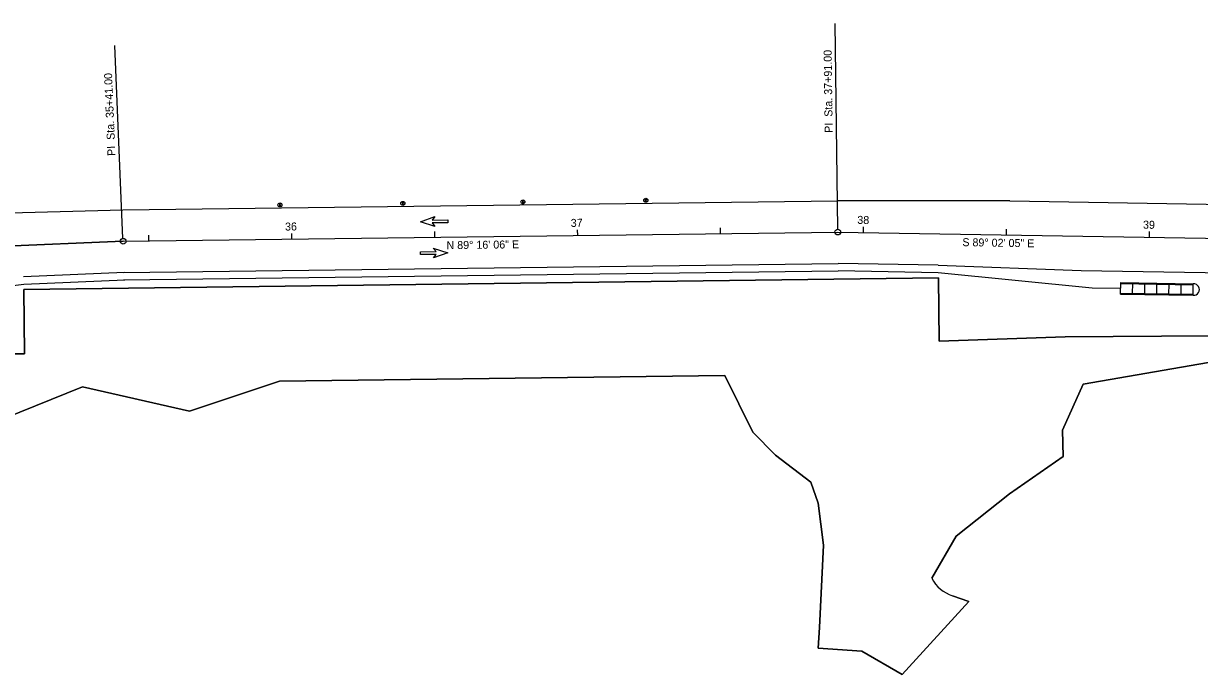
# Model space of a CAD drawing. Extents: x 2336268 to 2337731, y 629406 to 629656.
# Drawn here: x 2336849.2 to 2337260.6, y 629406.1 to 629633.9 of the extents above; entities that cross this region are included whole.
import ezdxf

# ---------------------------------------------------------------- set-up
doc = ezdxf.new("R2010")
doc.units = 0
for name, color, linetype in [('DR_P_Cells', 7, 'Continuous'), ('GE_P_CL_20', 7, 'Continuous'), ('GK_Drainage_Nodes', 7, 'Continuous'), ('MT_P_Cells', 7, 'Continuous'), ('MT_P_CL_Double_Solid', 7, 'Continuous'), ('MT_P_Edge_Line', 7, 'Continuous'), ('MT_P_PCB', 7, 'Continuous'), ('MT_P_Work_Area', 7, 'Continuous'), ('RD_P_Anchor_Assembly', 7, 'Continuous')]:
    doc.layers.add(name, color=color, linetype=linetype)

msp = doc.modelspace()

# ---------------------------------------------------------------- linework, layer by layer
at = {"layer": 'DR_P_Cells'}
for points in [[(2336981.99, 629571.33), (2336981.71, 629571.33), (2336981.72, 629570.53), (2336982, 629570.53)], [(2337023.99, 629571.87), (2337023.71, 629571.86), (2337023.72, 629571.06), (2337024, 629571.07)], [(2337066.98, 629572.41), (2337066.7, 629572.41), (2337066.71, 629571.61), (2337066.99, 629571.61)], [(2336938.99, 629570.78), (2336938.71, 629570.78), (2336938.72, 629569.98), (2336939, 629569.98)]]:
    msp.add_lwpolyline(points, dxfattribs=at)
for centre in [(2336981.89, 629570.93), (2337023.89, 629571.46), (2337066.89, 629572.01), (2336938.9, 629570.38)]:
    msp.add_circle(centre, 0.7, dxfattribs=at)
for centre in [(2336981.74, 629570.93), (2337023.74, 629571.46), (2337066.73, 629572.01), (2336938.74, 629570.38)]:
    msp.add_arc(centre, 0.474, 303.2466, 58.2169, dxfattribs=at)
at = {"layer": 'GE_P_CL_20'}
for p, q in [((2337134.02, 629561.88), (2337133.1, 629633.88)), ((2336884.01, 629558.69), (2336881.15, 629626.22)), ((2336884.06, 629557.69), (2337134.04, 629560.88)), ((2336893.06, 629557.81), (2336893.03, 629559.81)), ((2336943.06, 629558.44), (2336943.03, 629560.44)), ((2336993.05, 629559.08), (2336993.03, 629561.08)), ((2337043.05, 629559.72), (2337043.02, 629561.72)), ((2337093.04, 629560.36), (2337093.02, 629562.36)), ((2337134.04, 629560.88), (2337392.59, 629556.53)), ((2337143.04, 629560.73), (2337143.07, 629562.73)), ((2337193.03, 629559.89), (2337193.07, 629561.89)), ((2337243.02, 629559.05), (2337243.06, 629561.05)), ((2336608.8, 629546.02), (2336884.06, 629557.69))]:
    msp.add_line(p, q, dxfattribs=at)
for centre in [(2337134.04, 629560.88), (2336884.06, 629557.69)]:
    msp.add_circle(centre, 1, dxfattribs=at)
at = {"layer": 'GK_Drainage_Nodes'}
for p, q in [((2337023.89, 629571.46), (2337023.89, 629571.46)), ((2337023.89, 629571.46), (2337023.89, 629571.46)), ((2337023.89, 629571.46), (2337023.89, 629571.46)), ((2337023.89, 629571.46), (2337023.89, 629571.46)), ((2337023.89, 629571.46), (2337023.89, 629571.46)), ((2337066.89, 629572.01), (2337066.89, 629572.01)), ((2337066.89, 629572.01), (2337066.89, 629572.01)), ((2337066.89, 629572.01), (2337066.89, 629572.01)), ((2337066.89, 629572.01), (2337066.89, 629572.01)), ((2337066.89, 629572.01), (2337066.89, 629572.01)), ((2336938.9, 629570.38), (2336938.9, 629570.38)), ((2336938.9, 629570.38), (2336938.9, 629570.38)), ((2336938.9, 629570.38), (2336938.9, 629570.38)), ((2336938.9, 629570.38), (2336938.9, 629570.38)), ((2336938.9, 629570.38), (2336938.9, 629570.38)), ((2336981.89, 629570.93), (2336981.89, 629570.93)), ((2336981.89, 629570.93), (2336981.89, 629570.93)), ((2336981.89, 629570.93), (2336981.89, 629570.93)), ((2336981.89, 629570.93), (2336981.89, 629570.93)), ((2336981.89, 629570.93), (2336981.89, 629570.93))]:
    msp.add_line(p, q, dxfattribs=at)
for centre in [(2336981.89, 629570.93), (2337023.89, 629571.46), (2337066.89, 629572.01), (2336938.9, 629570.38)]:
    msp.add_circle(centre, 0.7, dxfattribs=at)
at = {"layer": 'MT_P_Cells'}
for p, q in [((2336988.1, 629564.52), (2336993.08, 629566.32)), ((2336988.1, 629564.52), (2336988.1, 629564.52)), ((2336993.12, 629562.85), (2336988.1, 629564.52)), ((2336993.08, 629566.32), (2336992.1, 629565.07)), ((2336992.1, 629565.07), (2336997.6, 629565.14)), ((2336997.61, 629564.14), (2336992.11, 629564.07)), ((2336992.11, 629564.07), (2336993.12, 629562.85)), ((2336997.6, 629565.14), (2336997.61, 629564.14)), ((2336997.6, 629564.64), (2336997.6, 629564.64)), ((2336993.58, 629554.09), (2336992.56, 629555.31)), ((2336992.56, 629555.31), (2336997.58, 629553.64)), ((2336988.08, 629554.02), (2336993.58, 629554.09)), ((2336988.09, 629553.02), (2336988.08, 629554.02)), ((2336993.59, 629553.09), (2336988.09, 629553.02)), ((2336997.58, 629553.64), (2336992.61, 629551.84)), ((2336992.61, 629551.84), (2336993.59, 629553.09))]:
    msp.add_line(p, q, dxfattribs=at)
at = {"layer": 'MT_P_CL_Double_Solid'}
for p, q in [((2336884.06, 629557.69), (2337134.04, 629560.88)), ((2337134.04, 629560.88), (2337392.59, 629556.53)), ((2336884.06, 629557.69), (2336608.8, 629546.02))]:
    msp.add_line(p, q, dxfattribs=at)
at = {"layer": 'MT_P_Edge_Line'}
for p, q in [((2336883.92, 629568.69), (2337133.9, 629571.88)), ((2337194.23, 629571.87), (2337133.9, 629571.88)), ((2337194.23, 629571.87), (2337392.79, 629568.53)), ((2336823.6, 629567.14), (2336883.92, 629568.69)), ((2336884.52, 629546.7), (2336849.21, 629545.2)), ((2336884.2, 629546.69), (2337134.18, 629549.88)), ((2337169.19, 629549.29), (2337134.18, 629549.88)), ((2337169.19, 629549.29), (2337219.21, 629547.45)), ((2337219.21, 629547.45), (2337392.39, 629544.53))]:
    msp.add_line(p, q, dxfattribs=at)
at = {"layer": 'MT_P_PCB'}
for p, q in [((2336884.23, 629544.19), (2337134.21, 629547.38)), ((2337134.13, 629547.39), (2337169.14, 629546.79)), ((2337169.14, 629546.79), (2337222.97, 629541.38)), ((2336795.56, 629535.92), (2336849.32, 629542.71)), ((2336849.32, 629542.71), (2336884.63, 629544.2)), ((2337222.97, 629541.38), (2337232.97, 629541.21))]:
    msp.add_line(p, q, dxfattribs=at)
at = {"layer": 'MT_P_Work_Area'}
for p, q in [((2336807.94, 629517.96), (2336849.56, 629518.31)), ((2336849.56, 629518.31), (2336807.94, 629517.96)), ((2337094.51, 629510.71), (2336938.72, 629508.72)), ((2336938.72, 629508.72), (2337094.51, 629510.71)), ((2337179.87, 629431.62), (2337156.6, 629406.06)), ((2337156.6, 629406.06), (2337179.87, 629431.62)), ((2337174.12, 629433.59), (2337179.87, 629431.62)), ((2337179.87, 629431.62), (2337174.12, 629433.59)), ((2337127.12, 629415.3), (2337127.63, 629422.51)), ((2337127.63, 629422.51), (2337127.12, 629415.3)), ((2337142.45, 629414.21), (2337127.12, 629415.3)), ((2337127.12, 629415.3), (2337142.45, 629414.21)), ((2337156.6, 629406.06), (2337142.45, 629414.21)), ((2337142.45, 629414.21), (2337156.6, 629406.06))]:
    msp.add_line(p, q, dxfattribs=at)
for points in [[(2337656.82, 629561.16), (2337621.49, 629549.43), (2337572.26, 629538.41), (2337522.5, 629528.64), (2337471.8, 629523.59), (2337421.03, 629519.2), (2337370.36, 629515.97), (2337319.82, 629515.06), (2337269.75, 629516.28), (2337219.92, 629507.62)], [(2337219.92, 629507.62), (2337269.75, 629516.28), (2337319.82, 629515.06), (2337370.36, 629515.97), (2337421.03, 629519.2), (2337471.8, 629523.59), (2337522.5, 629528.64), (2337572.26, 629538.41), (2337621.49, 629549.43), (2337656.82, 629561.16)], [(2336869.84, 629506.74), (2336820.4, 629486.81), (2336770.02, 629482.56), (2336719.73, 629484.58), (2336669.39, 629491.27), (2336618.42, 629486.44), (2336567.32, 629496.53), (2336516.11, 629500.76), (2336465.64, 629509.99), (2336415.8, 629519.34), (2336365.91, 629528.2), (2336337.53, 629544.91)], [(2336337.53, 629544.91), (2336365.91, 629528.2), (2336415.8, 629519.34), (2336465.64, 629509.99), (2336516.11, 629500.76), (2336567.32, 629496.53), (2336618.42, 629486.44), (2336669.39, 629491.27), (2336719.73, 629484.58), (2336770.02, 629482.56), (2336820.4, 629486.81), (2336869.84, 629506.74)], [(2336849.56, 629518.31), (2336849.27, 629540.75), (2337169.24, 629544.83), (2337169.53, 629522.77)], [(2337169.53, 629522.77), (2337169.24, 629544.83), (2336849.27, 629540.75), (2336849.56, 629518.31)], [(2337169.53, 629522.77), (2337213.56, 629524.22), (2337264.07, 629524.59)], [(2337264.07, 629524.59), (2337213.56, 629524.22), (2337169.53, 629522.77)], [(2337127.63, 629422.51), (2337129.02, 629451.35), (2337127.13, 629466.03), (2337124.66, 629473.33), (2337112.26, 629482.81), (2337104.29, 629490.88), (2337094.51, 629510.71)], [(2337094.51, 629510.71), (2337104.29, 629490.88), (2337112.26, 629482.81), (2337124.66, 629473.33), (2337127.13, 629466.03), (2337129.02, 629451.35), (2337127.63, 629422.51)], [(2336938.72, 629508.72), (2336907.23, 629498.19), (2336869.84, 629506.74)], [(2336869.84, 629506.74), (2336907.23, 629498.19), (2336938.72, 629508.72)], [(2337219.92, 629507.62), (2337212.65, 629491.58), (2337212.83, 629482.36), (2337194.05, 629469.25), (2337175.45, 629454.53), (2337166.88, 629439.72)], [(2337166.88, 629439.72), (2337175.45, 629454.53), (2337194.05, 629469.25), (2337212.83, 629482.36), (2337212.65, 629491.58), (2337219.92, 629507.62)]]:
    msp.add_lwpolyline(points, dxfattribs=at)
msp.add_arc((2337178.32, 629445.89), 13, 208.326, 251.1101, dxfattribs=at)
msp.add_arc((2337178.32, 629445.89), 13, 208.326, 251.1101, dxfattribs=at)
at = {"layer": 'RD_P_Anchor_Assembly'}
for p, q in [((2337232.94, 629539.21), (2337233, 629543.21)), ((2337233, 629543.21), (2337258.4, 629542.79)), ((2337233, 629542.88), (2337258.39, 629542.45)), ((2337237.17, 629539.48), (2337237.23, 629542.81)), ((2337241.41, 629539.41), (2337241.46, 629542.74)), ((2337245.64, 629539.33), (2337245.69, 629542.67)), ((2337249.87, 629539.26), (2337249.93, 629542.6)), ((2337254.1, 629539.19), (2337254.16, 629542.52)), ((2337258.33, 629538.79), (2337258.4, 629542.79)), ((2337232.94, 629539.55), (2337258.33, 629539.12)), ((2337232.94, 629539.21), (2337258.33, 629538.79))]:
    msp.add_line(p, q, dxfattribs=at)
msp.add_arc((2337258.52, 629540.78), 2.01, 264.6518, 93.4173, dxfattribs=at)

# ---------------------------------------------------------------- texts
at = {"layer": 'GE_P_CL_20'}
for s, rotation, p in [('PI  Sta. 37+91.00', 90.7317, (2337132.25, 629595.64)), ('PI  Sta. 35+41.00', 92.4289, (2336881.39, 629587.6)), ('36', 0.7317, (2336940.7, 629561.41)), ('37', 0.7317, (2337040.64, 629562.69)), ('38', 359.0346, (2337140.84, 629563.77)), ('39', 359.0346, (2337240.78, 629562.09)), ('N 89%%d 16\' 06" E', 0.7317, (2336997.19, 629554.89)), ('S 89%%d 02\' 05" E', 359.0346, (2337177.59, 629555.97))]:
    msp.add_text(s, height=2.8, rotation=rotation, dxfattribs=at).set_placement(p)

doc.saveas('drawing.dxf')
